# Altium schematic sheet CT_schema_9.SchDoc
size 147 x 119 mm
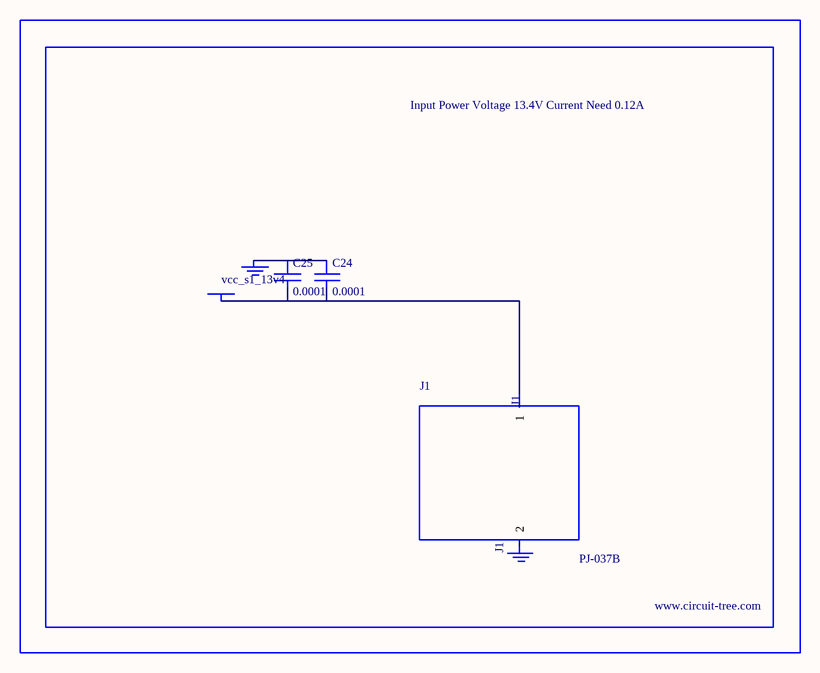
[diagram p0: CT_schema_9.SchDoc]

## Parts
BORDER8  (no value)
C24  0.0001  [EXV-9H]
C25  0.0001  [EXV-9H]
GND_INSTANCE_8_0  (no value)
GND_INSTANCE_8_1  (no value)
J1  PJ-037B  [PJ-037B_PACKAGE]
POWER_INSTANCE_8_0  vcc_s1_13v4

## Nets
NetC24_1: C24.1 C25.1 GND_INSTANCE_8_0.0(GND)
NetC24_2: C24.2 C25.2 J1.1 POWER_INSTANCE_8_0.0(PWR)

Not connected (* = marked no-connect by the designer): GND_INSTANCE_8_1 0(GND); J1 2

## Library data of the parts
BORDER8 = BORDER_PAGE8
C24 C25 = EDK107M035A9HAA
GND_INSTANCE_8_0 GND_INSTANCE_8_1 = GND
POWER_INSTANCE_8_0 = PWR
